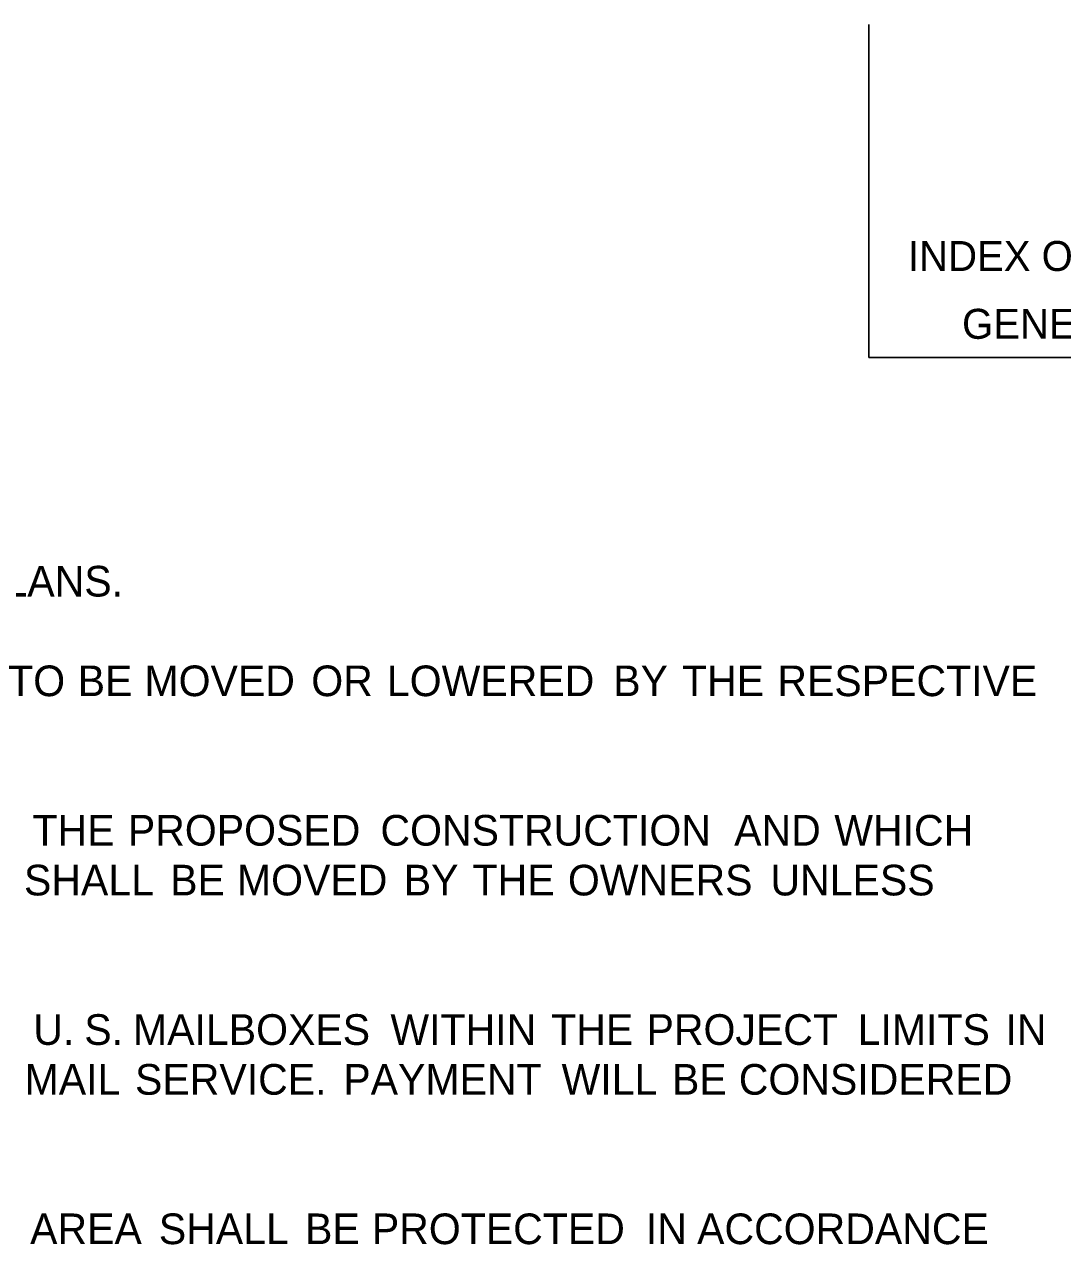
# Model space of a CAD drawing. Extents: x -1197 to 1681, y -1031 to 1021.
# Drawn here: x 919.6 to 1325.7, y 543 to 1020.6 of the extents above; entities that cross this region are included whole.
import ezdxf

# ---------------------------------------------------------------- set-up
doc = ezdxf.new("R2010")
doc.units = 0
doc.layers.add('Default', color=7, linetype='Continuous')
doc.layers.add('R_Border Prem', color=7, linetype='Continuous')

msp = doc.modelspace()

# ---------------------------------------------------------------- linework, layer by layer
at = {"layer": 'R_Border Prem'}
for p, q in [((1249.94, 1020.6), (1249.94, 892.6)), ((1249.94, 916.33), (1249.94, 890.16)), ((1249.94, 890.16), (1680.94, 890.16))]:
    msp.add_line(p, q, dxfattribs=at)

# ---------------------------------------------------------------- texts
at = {"layer": 'Default'}
for s, p in [(' PLANS.', (896.64, 796.66)), (' TO', (908.77, 757.66)), (' BE', (935.96, 757.66)), (' MOVED', (962.09, 757.66)), (' OR', (1027.34, 757.66)), (' LOWERED', (1056.92, 757.66)), (' BY', (1145.45, 757.66)), (' THE', (1172.35, 757.66)), (' RESPECTIVE', (1209.65, 757.66)), (' THE', (918.29, 699.16)), (' PROPOSED', (955.59, 699.16)), (' CONSTRUCTION', (1054.39, 699.16)), (' AND', (1192.75, 699.16)), (' WHICH', (1231.91, 699.16)), (' SHALL', (914.96, 679.66)), (' BE', (972.14, 679.66)), (' MOVED', (998.27, 679.66)), (' BY', (1063.52, 679.66)), (' THE', (1090.42, 679.66)), (' OWNERS', (1127.72, 679.66)), (' UNLESS', (1206.95, 679.66)), (' U.', (918.61, 621.16)), (' S.', (938.56, 621.16)), (' MAILBOXES', (957.6, 621.16)), (' WITHIN', (1058.29, 621.16)), (' THE', (1121.17, 621.16)), (' PROJECT', (1158.47, 621.16)), (' LIMITS', (1241.05, 621.16)), (' IN', (1298.86, 621.16)), (' MAIL', (915.21, 601.66)), (' SERVICE.', (958.4, 601.66)), (' PAYMENT', (1039.87, 601.66)), (' WILL', (1125.25, 601.66)), (' BE', (1168.43, 601.66)), (' CONSIDERED', (1194.56, 601.66)), (' AREA', (917.36, 543.16)), (' SHALL', (967.71, 543.16)), (' BE', (1024.9, 543.16)), (' PROTECTED', (1051.03, 543.16)), (' IN', (1158.2, 543.16)), (' ACCORDANCE', (1178.25, 543.16))]:
    msp.add_text(s, height=12, dxfattribs=at).set_placement(p)
at = {"layer": 'R_Border Prem'}
for s, p in [('INDEX OF SHEETS, GOVERNING SPECIFICATIONS ', (1265.21, 924.09)), ('GENERAL NOTES & STANDARD DRAWINGS', (1286.35, 897.54))]:
    msp.add_text(s, height=11.724, dxfattribs=at).set_placement(p)

doc.saveas('drawing.dxf')
